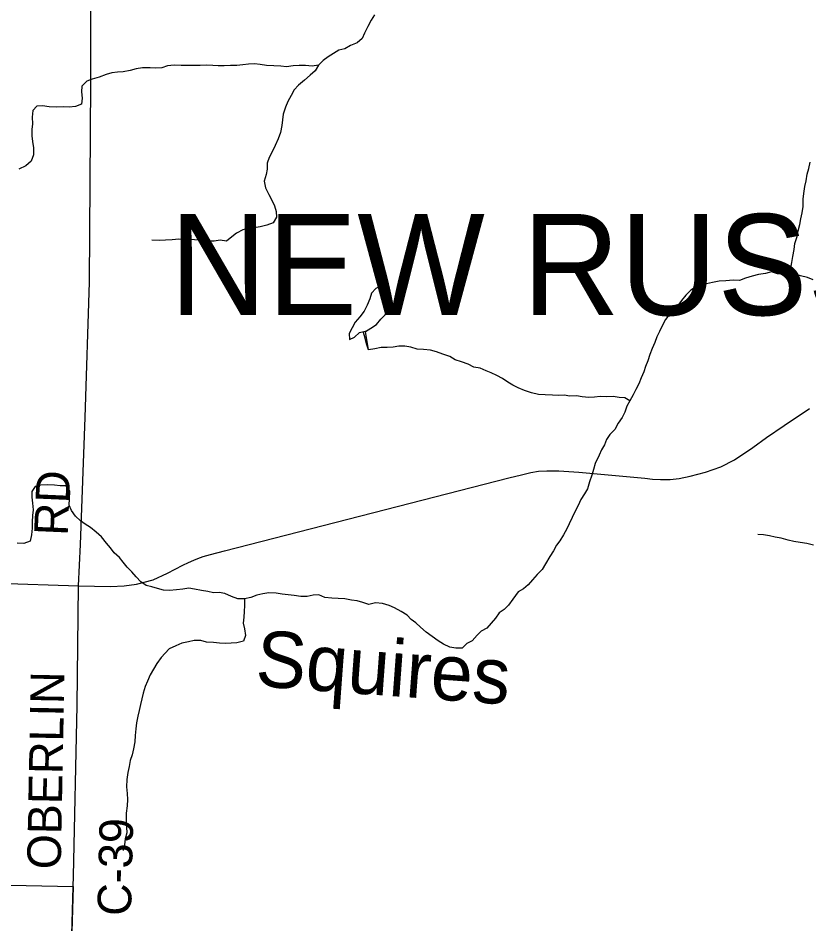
# Model space of a CAD drawing. Extents: x 1857828 to 2277390, y 930619 to 1324581.
# Drawn here: x 2051335 to 2058380, y 1202329 to 1210395 of the extents above; entities that cross this region are included whole.
import ezdxf

# ---------------------------------------------------------------- set-up
doc = ezdxf.new("R2010")
doc.units = 0
for name, color, linetype in [('GM_X_Corporation', 7, 'Continuous'), ('GM_X_County_Road', 7, 'Continuous'), ('GM_X_County_Road_Text', 7, 'Continuous'), ('GM_X_Minor_Lake', 7, 'Continuous'), ('GM_X_Minor_River', 7, 'Continuous'), ('GM_X_Minor_River_Text', 7, 'Continuous'), ('GM_X_Township_Road', 7, 'Continuous'), ('GM_X_Township_Text', 7, 'Continuous')]:
    doc.layers.add(name, color=color, linetype=linetype)

msp = doc.modelspace()

# ---------------------------------------------------------------- linework, layer by layer
at = {"layer": 'GM_X_Corporation'}
msp.add_lwpolyline([(2049034, 1202723), (2051825.2, 1202662.1), (2051790.6, 1201444.5)], dxfattribs=at)
at = {"layer": 'GM_X_County_Road'}
for points in [[(2051873.2, 1205339.4), (2051891.9, 1205707.8), (2051932, 1206839.5), (2051972, 1208043.4), (2051982.7, 1209818.5), (2051982.7, 1211799.1), (2051980, 1213035), (2051972, 1213683.6), (2051993.3, 1214588.5), (2052032.3, 1216016.4), (2052033.4, 1216053.9)], [(2051827.2, 1202753.7), (2051859.9, 1204274.4), (2051873.2, 1205339.4)], [(2051791.9, 1201487.6), (2051825.2, 1202662.1), (2051827.2, 1202753.7)]]:
    msp.add_lwpolyline(points, dxfattribs=at)
at = {"layer": 'GM_X_Minor_Lake'}
for points in [[(2054426.5, 1207608), (2054430.5, 1207604), (2054476.6, 1207633.8), (2054526.7, 1207667.7), (2054567, 1207715.6), (2054605.1, 1207753.5), (2054647.3, 1207801.4), (2054663.5, 1207851.5), (2054655.7, 1207903.6), (2054643.9, 1207953.8), (2054626.1, 1208004), (2054572.2, 1208012.3), (2054522.1, 1207988.4), (2054483.9, 1207946.5), (2054469.7, 1207894.5), (2054445.5, 1207838.4), (2054417.2, 1207784.4), (2054379, 1207736.5), (2054338.8, 1207688.6), (2054310.6, 1207636.6), (2054284.4, 1207586.6), (2054286.2, 1207534.5), (2054332.3, 1207554.3)], [(2054455.7, 1207440.3), (2054430.5, 1207604), (2054476.6, 1207633.8), (2054526.7, 1207667.7), (2054567, 1207715.6), (2054605.1, 1207753.5), (2054647.3, 1207801.4), (2054663.5, 1207851.5), (2054655.7, 1207903.6), (2054643.9, 1207953.8), (2054626.1, 1208004), (2054572.2, 1208012.3), (2054522.1, 1207988.4), (2054483.9, 1207946.5), (2054469.7, 1207894.5), (2054445.5, 1207838.4), (2054417.2, 1207784.4), (2054379, 1207736.5), (2054338.8, 1207688.6), (2054310.6, 1207636.6), (2054284.4, 1207586.6), (2054286.2, 1207534.5), (2054332.3, 1207554.3)], [(2054332.3, 1207554.3), (2054376.4, 1207594.2), (2054426.5, 1207608)]]:
    msp.add_lwpolyline(points, dxfattribs=at)
at = {"layer": 'GM_X_Minor_River'}
for points in [[(2054510.3, 1210424.1), (2054480.1, 1210378.1), (2054449.8, 1210320.1), (2054421.6, 1210260.1), (2054401.4, 1210214.1), (2054355.2, 1210174.2), (2054297.1, 1210150.4), (2054247, 1210120.6), (2054193, 1210110.8), (2054144.8, 1210078.9), (2054096.7, 1210049.1), (2054052.6, 1210019.2), (2054010.4, 1209977.3)], [(2054010.4, 1209977.3), (2053954.4, 1209967.6), (2053896.4, 1209973.8), (2053840.4, 1209972.1), (2053786.4, 1209970.3), (2053726.3, 1209962.6), (2053674.4, 1209966.8), (2053612.4, 1209971.1), (2053548.4, 1209973.4), (2053490.4, 1209981.7), (2053440.4, 1209988), (2053388.4, 1209986.2), (2053336.4, 1209978.4), (2053284.4, 1209974.7), (2053226.4, 1209972.9), (2053170.4, 1209971.2), (2053118.4, 1209971.4), (2053068.4, 1209973.6), (2053012.4, 1209975.9), (2052956.4, 1209974.2), (2052900.4, 1209974.4), (2052848.4, 1209972.7), (2052788.4, 1209972.9), (2052726.4, 1209977.2), (2052666.4, 1209969.5), (2052616.3, 1209951.7), (2052562.3, 1209949.9), (2052512.3, 1209952.2), (2052442.3, 1209952.5), (2052388.2, 1209942.7), (2052332.2, 1209928.9), (2052270.1, 1209917.2), (2052220.1, 1209913.4), (2052170.1, 1209907.6), (2052120, 1209891.8), (2052057.9, 1209870.1), (2051995.9, 1209850.3), (2051947.8, 1209832.5), (2051901.6, 1209788.6), (2051899.4, 1209738.5), (2051905.1, 1209682.3), (2051898.9, 1209628.2), (2051846.8, 1209608.4), (2051790.8, 1209602.7), (2051740.8, 1209604.9), (2051678.8, 1209603.2), (2051610.8, 1209605.5), (2051552.9, 1209613.8), (2051500.8, 1209612), (2051466.7, 1209572.1), (2051460.4, 1209512), (2051462.2, 1209453.8), (2051458, 1209403.8), (2051457.7, 1209347.6), (2051463.5, 1209297.5), (2051471.3, 1209239.3), (2051473, 1209179.2), (2051450.8, 1209121.1), (2051402.6, 1209079.3), (2051342.5, 1209049.5)], [(2054010.4, 1209977.3), (2053982.2, 1209925.3), (2053938, 1209887.5), (2053887.8, 1209843.6), (2053833.7, 1209797.7), (2053795.5, 1209755.8), (2053767.3, 1209705.8), (2053739, 1209651.8), (2053716.8, 1209601.8), (2053696.6, 1209539.8), (2053690.4, 1209489.7), (2053684.1, 1209437.6), (2053671.9, 1209377.5), (2053651.7, 1209321.5), (2053625.4, 1209259.5), (2053599.2, 1209205.4), (2053573, 1209153.5), (2053554.7, 1209103.4), (2053552.5, 1209051.3), (2053544.3, 1209001.2), (2053528.1, 1208943.2), (2053537.8, 1208883), (2053567.6, 1208824.7), (2053597.3, 1208768.5), (2053619.2, 1208722.3), (2053634.9, 1208674.1), (2053636.7, 1208621.9), (2053606.5, 1208572), (2053550.4, 1208552.2), (2053492.4, 1208536.4), (2053438.3, 1208526.6), (2053388.3, 1208520.9), (2053336.3, 1208509.1), (2053282.1, 1208481.3), (2053240, 1208447.4), (2053191.8, 1208409.5), (2053135.9, 1208417.8), (2053081.8, 1208408), (2053023.8, 1208410.3), (2052957.9, 1208416.6), (2052905.9, 1208420.8), (2052835.9, 1208425.2), (2052767.9, 1208425.5), (2052707.9, 1208419.8), (2052647.9, 1208418), (2052591.9, 1208414.3), (2052527.9, 1208416.6)], [(2058248.6, 1208119.2), (2058218.9, 1208167.8), (2058227.1, 1208217.9), (2058237.3, 1208271.9), (2058247.6, 1208334), (2058255.8, 1208388.1), (2058274, 1208450.2), (2058284.3, 1208500.2), (2058298.5, 1208556.3), (2058306.7, 1208606.4), (2058320.9, 1208660.4), (2058327.2, 1208718.5), (2058329.4, 1208782.7), (2058333.7, 1208834.8), (2058343.9, 1208894.8), (2058354.1, 1208946.9), (2058364.4, 1209005), (2058378.6, 1209057.1), (2058390.8, 1209111.1)], [(2058199.8, 1208112.5), (2058150.6, 1208113.1), (2058098.6, 1208119), (2058046.5, 1208135), (2057992.5, 1208120.9), (2057930.5, 1208112.8), (2057874.6, 1208098.7), (2057814.6, 1208080.5), (2057760.6, 1208058.4), (2057704.6, 1208062.3), (2057638.6, 1208056.2), (2057580.6, 1208052.1), (2057520.7, 1208040), (2057466.7, 1208029.9), (2057416.7, 1208021.8), (2057368.7, 1207999.7), (2057326.8, 1207971.6), (2057284.9, 1207929.4), (2057245, 1207879.3), (2057213.1, 1207835.1), (2057177.2, 1207797), (2057141.3, 1207760.9), (2057101.4, 1207710.7), (2057071.5, 1207654.5), (2057047.6, 1207604.4), (2057023.7, 1207558.2), (2057007.9, 1207506.1), (2056984, 1207453.9), (2056964.1, 1207399.8), (2056944.2, 1207343.6), (2056924.3, 1207293.5), (2056908.4, 1207245.4), (2056886.6, 1207191.2), (2056864.7, 1207139.1), (2056838.8, 1207088.9), (2056814.9, 1207040.8), (2056785, 1206988.6), (2056759.1, 1206938.4), (2056739.3, 1206886.3), (2056717.4, 1206840.2), (2056681.5, 1206788), (2056649.6, 1206731.8), (2056605.7, 1206687.7), (2056577.8, 1206643.5), (2056559.9, 1206595.4), (2056532, 1206551.2), (2056510.1, 1206503.1), (2056474.3, 1206428.9), (2056462.4, 1206376.8), (2056446.5, 1206324.6), (2056424.7, 1206266.4), (2056408.8, 1206202.3), (2056380.9, 1206158.1), (2056349, 1206110), (2056323.1, 1206055.8), (2056291.3, 1205993.6), (2056269.4, 1205947.5), (2056243.5, 1205893.3), (2056223.6, 1205847.2), (2056193.7, 1205795.1), (2056161.9, 1205740.9), (2056132, 1205700.7), (2056104.1, 1205652.6), (2056072.2, 1205600.4), (2056032.3, 1205534.2), (2056004.4, 1205484.1), (2055958.5, 1205439.9), (2055918.7, 1205393.7), (2055878.7, 1205349.6), (2055838.8, 1205313.4), (2055790.9, 1205285.3), (2055741, 1205221.1), (2055703.2, 1205166.9), (2055665.2, 1205128.8), (2055619.3, 1205100.6), (2055587.4, 1205050.5), (2055549.5, 1205008.3), (2055509.6, 1204964.2), (2055461.7, 1204936.1), (2055425.8, 1204899.9), (2055379.9, 1204849.7), (2055331.9, 1204825.6), (2055290, 1204783.5), (2055234, 1204785.4), (2055182, 1204793.3), (2055125.9, 1204819.3), (2055075.8, 1204851.3), (2055023.7, 1204889.3), (2054971.6, 1204927.3), (2054919.5, 1204971.4), (2054877.4, 1205011.4), (2054837.4, 1205041.4), (2054801.3, 1205079.4), (2054747.2, 1205111.4), (2054689.1, 1205143.4), (2054641.1, 1205163.4), (2054581, 1205181.4), (2054519, 1205187.3), (2054459, 1205173.2), (2054407, 1205191.1)], [(2058418.7, 1208065.3), (2058366.7, 1208085.3), (2058304.6, 1208099.3), (2058248.6, 1208119.2), (2058199.7, 1208112.4)], [(2054455.7, 1207440.3), (2054439.6, 1207494.4), (2054425.5, 1207544.5), (2054413.3, 1207596.6)], [(2056785, 1206988.6), (2056741, 1207014.6), (2056689, 1207016.5), (2056634.9, 1207024.5), (2056580.9, 1207022.4), (2056518.9, 1207026.3), (2056468.9, 1207020.2), (2056418.9, 1207018.1), (2056360.9, 1207024.1), (2056310.9, 1207032), (2056250.9, 1207027.9), (2056198.8, 1207037.9), (2056144.8, 1207035.8), (2056094.8, 1207037.7), (2056030.8, 1207039.6), (2055970.8, 1207043.6), (2055908.8, 1207059.5), (2055846.7, 1207079.5), (2055788.6, 1207103.4), (2055742.6, 1207127.4), (2055698.5, 1207153.4), (2055650.4, 1207185.4), (2055600.4, 1207211.4), (2055550.3, 1207235.4), (2055504.3, 1207255.4), (2055452.2, 1207277.4), (2055396.2, 1207287.3), (2055344.1, 1207313.3), (2055284, 1207335.3), (2055230, 1207353.2), (2055181.9, 1207383.2), (2055119.9, 1207403.2), (2055063.8, 1207423.1), (2055007.8, 1207437.1), (2054945.8, 1207443), (2054889.7, 1207447), (2054833.7, 1207464.9), (2054781.7, 1207474.9), (2054727.7, 1207474.8), (2054675.7, 1207464.7), (2054623.7, 1207462.6), (2054569.7, 1207462.5), (2054511.7, 1207450.4), (2054455.7, 1207440.3)], [(2054407, 1205191.1), (2054354.9, 1205205.1), (2054304.9, 1205213), (2054246.9, 1205223), (2054186.9, 1205226.9), (2054128.8, 1205228.8), (2054068.8, 1205236.8), (2054012.8, 1205260.7), (2053962.8, 1205256.6), (2053908.8, 1205244.5), (2053854.8, 1205244.5), (2053794.8, 1205254.4), (2053740.7, 1205260.3), (2053688.7, 1205264.3), (2053634.7, 1205274.2), (2053568.7, 1205276.1), (2053514.7, 1205268), (2053462.7, 1205255.9), (2053408.8, 1205235.8), (2053352.8, 1205223.7), (2053292.8, 1205223.6), (2053234.7, 1205243.6), (2053176.6, 1205271.6), (2053126.6, 1205281.5), (2053074.6, 1205277.4), (2053024.6, 1205289.4), (2052968.6, 1205297.3), (2052906.5, 1205311.3), (2052856.5, 1205319.2), (2052802.5, 1205309.1), (2052746.5, 1205303), (2052684.5, 1205296.9), (2052630.5, 1205300.8), (2052576.5, 1205314.8), (2052526.4, 1205330.8), (2052476.4, 1205342.7), (2052428.3, 1205376.7), (2052386.2, 1205418.8), (2052348.1, 1205464.8), (2052308, 1205504.9), (2052271.9, 1205550.9), (2052237.8, 1205590.9), (2052191.7, 1205633), (2052157.6, 1205679.1), (2052123.5, 1205721.1), (2052079.4, 1205775.1), (2052031.3, 1205817.2), (2051981.1, 1205859.2), (2051933.1, 1205889.2), (2051891, 1205917.2), (2051846.9, 1205961.2), (2051810.8, 1206009.3), (2051790.7, 1206057.4), (2051792.5, 1206115.5), (2051796.4, 1206181.7), (2051764.3, 1206229.7), (2051710.2, 1206231.7), (2051660.2, 1206235.6), (2051600.2, 1206239.5), (2051536.2, 1206235.4), (2051486.2, 1206223.3), (2051456.3, 1206179.2), (2051456.5, 1206129.1), (2051462.6, 1206075), (2051468.7, 1206016.8), (2051462.8, 1205966.7), (2051459, 1205910.6), (2051459.1, 1205852.4), (2051455.2, 1205794.3), (2051443.4, 1205738.2), (2051387.4, 1205718), (2051327.4, 1205720)], [(2058420.2, 1205702), (2058362.2, 1205715.9), (2058302.1, 1205725.9), (2058244.1, 1205735.8), (2058194.1, 1205747.8), (2058134, 1205765.7), (2058078, 1205773.7), (2058028, 1205783.6), (2057975.9, 1205793.6), (2057923.9, 1205797.5)], [(2053352.8, 1205223.7), (2053350.9, 1205165.6), (2053349, 1205111.4), (2053347.2, 1205061.3), (2053341.3, 1205007.2), (2053351.4, 1204957.1), (2053359.5, 1204897), (2053341.7, 1204846.8), (2053283.7, 1204832.7), (2053233.7, 1204830.6), (2053179.7, 1204826.6), (2053129.7, 1204828.5), (2053075.7, 1204834.4), (2053013.6, 1204838.3), (2052961.6, 1204852.3), (2052903.6, 1204852.2), (2052853.6, 1204842.1), (2052793.6, 1204828), (2052739.7, 1204805.9), (2052681.8, 1204777.7), (2052643.8, 1204739.6), (2052609.9, 1204701.4), (2052570, 1204649.3), (2052540.2, 1204597.1), (2052512.3, 1204547), (2052488.4, 1204490.8), (2052466.5, 1204442.7), (2052448.7, 1204384.5), (2052436.8, 1204334.4), (2052424.9, 1204282.2), (2052415, 1204230.1), (2052401.1, 1204178), (2052391.3, 1204119.8), (2052385.4, 1204065.7), (2052377.5, 1204007.5), (2052373.7, 1203951.4), (2052363.8, 1203887.2), (2052349.9, 1203835.1), (2052334.1, 1203784.9), (2052324.2, 1203730.8), (2052312.3, 1203678.7), (2052304.5, 1203614.5), (2052300.6, 1203550.4), (2052306.7, 1203490.2), (2052310.9, 1203436.1), (2052307, 1203382), (2052299.2, 1203315.8), (2052299.3, 1203247.7), (2052301.4, 1203191.5), (2052303.6, 1203141.4), (2052289.7, 1203087.3), (2052281.8, 1203033.1), (2052269.9, 1202983)]]:
    msp.add_lwpolyline(points, dxfattribs=at)
at = {"layer": 'GM_X_Township_Road'}
for points in [[(2051873.2, 1205339.4), (2052158.9, 1205334.1), (2052279, 1205339.4), (2052391.1, 1205355.4), (2052537.3, 1205394.2), (2052664.7, 1205453.4), (2052803.9, 1205522.7), (2052853.7, 1205547.2), (2052899.4, 1205569.6), (2052935.3, 1205583.9), (2052985.1, 1205602.3), (2053048.9, 1205618.9), (2053172.5, 1205652), (2055706.7, 1206300.2), (2055820.3, 1206329.2), (2055902.1, 1206349.9), (2055969.9, 1206360.5), (2056043.8, 1206363.1), (2056151.7, 1206364), (2056331.6, 1206351.4), (2056919.6, 1206298.1), (2056987.6, 1206290.7), (2057057.5, 1206287.3), (2057143.5, 1206288), (2057223.3, 1206296.7), (2057323.1, 1206315.5), (2057458.6, 1206350.7), (2057594.1, 1206399.9), (2057717.4, 1206461.1), (2057880.4, 1206570.6), (2058003.5, 1206659.8), (2058158.4, 1206767.3), (2058385, 1206917.5)], [(2046329.6, 1205535), (2047609.1, 1205483.8), (2048570.4, 1205453.7), (2048870.2, 1205440.1), (2049100.1, 1205430), (2049364, 1205416.2), (2051147.2, 1205363.4), (2051873.2, 1205339.4)]]:
    msp.add_lwpolyline(points, dxfattribs=at)

# ---------------------------------------------------------------- texts
at = {"layer": 'GM_X_County_Road_Text'}
for s, rotation, p in [('RD', 87.53137, (2051776.5, 1205782.2)), ('OBERLIN', 88.89478, (2051714.7, 1202813.6)), ('C-39', 88.62866, (2052340.6, 1202397.9))]:
    msp.add_text(s, height=300, rotation=rotation, dxfattribs=at).set_placement(p)
at = {"layer": 'GM_X_Minor_River_Text'}
msp.add_text('Squires', height=500.25, rotation=355.77716, dxfattribs=at).set_placement((2053440.8, 1204448.2))
at = {"layer": 'GM_X_Township_Text'}
msp.add_text('NEW RUSSIA', height=900, rotation=0.00001, dxfattribs=at).set_placement((2052684.5, 1207750.5))

doc.saveas('drawing.dxf')
